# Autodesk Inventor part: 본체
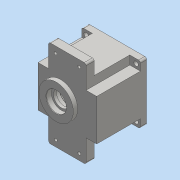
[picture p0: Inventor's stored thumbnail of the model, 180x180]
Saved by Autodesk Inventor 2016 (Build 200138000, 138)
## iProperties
Created: 2020-08
Part Number: 본체
Material: 일반
Document SubType Name: Modeling
Designer: User
Density: 1 g/cm^3
Appearance: 기본값
Author: User
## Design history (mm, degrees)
sketch "스케치1"
  geometry: L1 (30, 70)-(-30, 70); L2 (-30, 70)-(-30, -70); L3 (-30, -70)-(30, -70); L4 (30, -70)-(30, 70); L5 (47, 47)-(-47, 47); L6 (-47, 47)-(-47, -47); L7 (-47, -47)-(47, -47); L8 (47, -47)-(47, 47); 5 further points
  constraints: 16 end point, 4 midpoint, 4 parallel, 2 horizontal, 2 horizontal alignment, 2 perpendicular, 2 vertical alignment
  dimensions: "d0" = 60 distance of L2.end L3.end; "d1" = 140 distance of L3.end L1.start; "d2" = 94 distance of L7.end L6.end; "d3" = 94 distance of L6.end L5.end
extrude "돌출1" new body sketch "스케치1" distance "d4" = 13; taper "d5" = 0 deg
sketch "스케치2"
  geometry: L1 (-30, 47)-(-47, 47) reference; L2 (-47, 47)-(-47, -47) reference; L3 (-47, -47)-(-30, -47) reference; L4 (-30, -47)-(-30, -70) reference; L5 (-30, -70)-(30, -70) reference; L6 (30, -70)-(30, -47) reference; L7 (30, -47)-(47, -47) reference; L8 (47, -47)-(47, 47) reference; L9 (47, 47)-(30, 47) reference; L10 (30, 47)-(30, 70) reference; L11 (30, 70)-(-30, 70) reference; L12 (-30, 70)-(-30, 47) reference; L13 (47, -47)-(47, 47) reference; L14 (-47, 47)-(-47, -47) reference; L15 (47, 47)-(-47, 47); L16 (-47, 47)-(-47, -47); L17 (-47, -47)-(47, -47); L18 (47, -47)-(47, 47); 1 further point
  constraints: 8 end point, 2 parallel, 1 horizontal, 1 perpendicular
extrude "돌출2" join sketch "스케치2" distance "d6" = 67; taper "d7" = 0 deg
sketch "스케치3"
  geometry: L1 (-30, -70)-(-30, -47) reference; L2 (30, -70)-(-30, -70) reference; L3 (30, -47)-(30, -70) reference; L4 (47, -47)-(30, -47) reference; L5 (47, 47)-(47, -47) reference; L6 (30, 47)-(47, 47) reference; L7 (30, 70)-(30, 47) reference; L8 (-30, 70)-(30, 70) reference; L9 (-30, 47)-(-30, 70) reference; L10 (-47, 47)-(-30, 47) reference; L11 (-47, -47)-(-47, 47) reference; L12 (-30, -47)-(-47, -47) reference; L13 (47, 47)-(30, 47); L14 (30, 47)-(30, 33); L15 (30, 33)-(47, 33); L16 (47, 33)-(47, 47); L17 (30, 70)-(30, 47) reference; L18 (47, 47)-(47, -47) reference; L19 (47, -47)-(30, -47); L20 (30, -47)-(30, -33); L21 (30, -33)-(47, -33); L22 (47, -33)-(47, -47); L23 (-47, 47)-(-30, 47); L24 (-30, 47)-(-30, 33); L25 (-30, 33)-(-47, 33); L26 (-47, 33)-(-47, 47); L27 (-47, -47)-(-30, -47); L28 (-30, -47)-(-30, -33); L29 (-30, -33)-(-47, -33); L30 (-47, -33)-(-47, -47); L31 (30, -47)-(30, -70) reference; L32 (-30, 47)-(-30, 70) reference; L33 (-30, -70)-(-30, -47) reference; 1 further point
  constraints: 32 end point, 8 parallel, 4 collinear, 4 horizontal, 4 perpendicular, 3 equal length
  dimensions: "d8" = 14 distance of L15.end L5.start
extrude "돌출3" cut sketch "스케치3" distance "d9" = 70; taper "d10" = 0 deg
sketch "스케치4"
  geometry: C1 r 43 at (0, 0); 1 further point
  constraints: 1 centre point, 1 coincident
  dimensions: "d11" = 86 diameter of C1
extrude "돌출4" cut sketch "스케치4" distance "d12" = 9; taper "d13" = 0 deg
sketch "스케치5"
  geometry: C1 r 40 at (0, 0); 1 further point
  constraints: 1 centre point, 1 coincident
  dimensions: "d14" = 80 diameter of C1
extrude "돌출5" cut sketch "스케치5" distance "d15" = 62; taper "d16" = 0 deg
sketch "스케치6"
  geometry: C1 r 21 at (-11, 0); C2 r 15 at (20, 0); 1 further point
  constraints: 2 centre point, 2 horizontal alignment
  dimensions: "d17" = 42 diameter of C1; "d18" = 30 diameter of C2; "d19" = 11 distance of point (0, 0) C1.centre; "d20" = 20 distance of C2.centre point (0, 0)
extrude "돌출6" join sketch "스케치6" distance "d21" = 7; taper "d22" = 0 deg
sketch "스케치7"
  geometry: A1 r 4 centre (0, 36) between (-3.995, 36.19) and (3.995, 36.19); A2 r 4 centre (0, -36) between (3.995, -36.19) and (-3.995, -36.19); A3 r 3 centre (6.992, 36.333) between (7.559, 39.279) and (3.995, 36.19); A4 r 3 centre (-6.992, 36.333) between (-3.995, 36.19) and (-7.559, 39.279); A5 r 3 centre (-6.992, -36.333) between (-7.559, -39.279) and (-3.995, -36.19); A6 r 3 centre (6.992, -36.333) between (3.995, -36.19) and (7.559, -39.279); A7 r 40 centre (0, 0) between (7.559, -39.279) and (-7.559, -39.279) reference; 1 further point
  constraints: 16 point on circle, 8 tangent, 6 centre point, 4 equal radius, 2 vertical alignment
  dimensions: "d23" = 8 diameter of A1; "d24" = 36 distance of A1.centre point (0, 0); "d25" = 36 distance of A2.centre point (0, 0); "d44" = 6 diameter of A3
sketch "스케치8"
  geometry: C1 r 27.5 at (-11, 0); A1 r 21 centre (-11, 0) between (7.984, 8.978) and (7.984, -8.978) reference; A2 r 15 centre (20, 0) between (7.984, -8.978) and (7.984, 8.978) reference; 1 further point
  constraints: 1 centre point, 1 coincident
  dimensions: "d26" = 55 diameter of C1
extrude "돌출7" join sketch "스케치8" distance "d27" = 7; taper "d28" = 0 deg
sketch "스케치9"
  geometry: C1 r 27.5 at (0, 0) reference; C2 r 16 at (0, 0); 1 further point
  constraints: 1 centre point, 1 coincident
  dimensions: "d29" = 32 diameter of C2
extrude "돌출8" cut sketch "스케치9" distance "d30" = 8.3; taper "d31" = 0 deg
sketch "스케치10"
  geometry: C1 r 16 at (0, 0) reference; C2 r 12.5 at (0, 0); 1 further point
  constraints: 1 centre point, 1 coincident
  dimensions: "d32" = 25 diameter of C2
extrude "돌출9" cut sketch "스케치10" distance "d33" = 4.7; taper "d34" = 0 deg
sketch "스케치11"
  geometry: C1 r 12.5 at (0, 0) reference; C2 r 17.5 at (0, 0); 1 further point
  constraints: 1 centre point, 1 coincident
  dimensions: "d35" = 35 diameter of C2
extrude "돌출10" cut sketch "스케치11" distance "d36" = 10; taper "d37" = 0 deg
sketch "스케치12"
  geometry: C1 r 17.5 at (-11, 0) reference; C2 r 11 at (20, 0); A1 r 21 centre (-11, 0) between (7.984, 8.978) and (7.984, -8.978) reference; A2 r 15 centre (20, 0) between (7.984, -8.978) and (7.984, 8.978) reference; 1 further point
  constraints: 1 centre point, 1 coincident
  dimensions: "d38" = 22 diameter of C2
extrude "돌출11" cut sketch "스케치12" distance "d39" = 7; taper "d40" = 0 deg
sketch "스케치13"
  geometry: C1 r 11 at (0, 0) reference; C2 r 9.5 at (0, 0); 1 further point
  constraints: 1 centre point, 1 coincident
  dimensions: "d41" = 19 diameter of C2
extrude "돌출12" cut sketch "스케치13" distance "d42" = 3; taper "d43" = 0 deg
extrude "돌출13" join sketch "스케치7" stored distance "d45" = 3; taper "d46" = 0 deg
chamfer "모따기1" distance "d47" = 0.8; stored, may be unused: second distance "d48" = 2, angle "d49" = 30 deg
fillet "모깎기1" dims "d50" = 3
fillet "모깎기2" dims "d51" = 3
chamfer "모따기2" distance "d52" = 1; stored, may be unused: second distance "d53" = 2, angle "d54" = 45 deg
chamfer "모따기3" distance "d55" = 1; stored, may be unused: second distance "d56" = 2, angle "d57" = 45 deg
sketch "스케치14"
  geometry: 5 further points
  dimensions: "d58" = 60 vertical distance of point (0, 0) point (19, 60); "d59" = 60 vertical distance of point (19, -60) point (0, 0); "d60" = 60 vertical distance of point (0, 0) point (-18.556, 60); "d61" = 60 vertical distance of point (0, 0) point (-19, -60); "d62" = 19 horizontal distance of point (0, 0) point (19, -60); "d63" = 19 horizontal distance of point (-19, -60) point (0, 0); "d64" = 19 horizontal distance of point (19, 60) point (0, 0); "d65" = 18.55564 horizontal distance of point (-18.556, 60) point (0, 0)
hole "구멍1" sketch "스케치14" at (19, -60), (19, 60), (-18.556, 60), (-19, -60) diameter "d66" = 4.5; stored, may be unused: countersink angle "d70" = 90 deg, drill point angle "d72" = 118 deg; dims "d67" = 6, "d68" = 10, "d69" = 5, "d71" = 20
sketch "스케치15"
  geometry: 5 further points
  dimensions: "d73" = 40 horizontal distance of point (0, 0) point (40, 40); "d74" = 40 horizontal distance of point (40, -40) point (0, 0); "d75" = 40 horizontal distance of point (-40, -40) point (0, 0); "d76" = 40 horizontal distance of point (-40, 40) point (0, 0); "d77" = 40 horizontal distance of point (0, 0) point (-40, -40); "d78" = 40 horizontal distance of point (40, -40) point (0, 0); "d79" = 40 horizontal distance of point (40, 40) point (0, 0); "d80" = 40 horizontal distance of point (-40, 40) point (0, 0)
hole "구멍2" sketch "스케치15" at (40, 40), (-40, 40), (-40, -40), (40, -40) diameter "d81" = 7; stored, may be unused: countersink angle "d85" = 90 deg, drill point angle "d87" = 118 deg; dims "d82" = 6, "d83" = 10, "d84" = 5, "d86" = 20
sketch "스케치16"
  geometry: 3 further points
  constraints: 2 vertical alignment
  dimensions: "d88" = 36 distance of point (0, 0) point (0, -36); "d89" = 36 distance of point (0, 36) point (0, 0)
hole "구멍3" sketch "스케치16" at (0, -36), (0, 36) diameter "d90" = 3.242; stored, may be unused: countersink angle "d94" = 90 deg, drill point angle "d96" = 118 deg; dims "d91" = 7, "d92" = 10, "d93" = 5, "d95" = 9
sketch "스케치17"
  geometry: L1 (0, 0)-(66, 0) reference; L2 (-11, 70)-(-11, 80) reference; L3 (-11, 70)-(0, 70) reference; L4 (0, 70)-(0, 0) reference; L5 (0, 0)-(66, 0) reference; L6 (66, 0)-(66, 70) reference; L7 (66, 70)-(77, 70) reference; L8 (77, 80)-(77, 70) reference; L9 (-11, 80)-(77, 80) reference; 3 further points
  constraints: 1 midpoint, 1 vertical alignment, 1 other
  dimensions: "d97" = 40 distance from line of L9 point (33, 40)
feature "엠보싱1" sketch "스케치17" dims "d0" = 60, "d1" = 140, "d2" = 94, "d3" = 94, "d98" = 0.5, "d99" = 0
node "솔리드1"
node "투영된 루프1"
node "투영된 루프2"
node "투영된 루프3"
node "투영된 루프4"
node "투영된 루프5"
node "투영된 루프6"
node "투영된 루프7"
node "투영된 루프8"
node "투영된 루프9"
